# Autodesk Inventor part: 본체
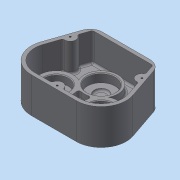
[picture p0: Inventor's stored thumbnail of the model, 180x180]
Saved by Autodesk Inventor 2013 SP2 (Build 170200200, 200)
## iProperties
Created: 2014-12
Part Number: 본체
Material: 일반
Document SubType Name: Modeling
Designer: dgall
Density: 1 g/cm^3
Author: dgall
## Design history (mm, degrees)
sketch "스케치1"
  geometry: L1 (-47, 36)-(47, 36); L2 (0, 36)-(0, -137); L3 (-32.257, -68.257)-(32.257, -68.257); L4 (0, 0)-(-32.257, -32.257); L5 (0, 0)-(32.257, -32.257); L6 (-47, 36)-(-66.327, -20.629); L7 (47, 36)-(66.327, -20.629); A1 r 36 centre (-32.257, -32.257) between (-66.327, -20.629) and (-32.257, -68.257); A2 r 36 centre (32.257, -32.257) between (32.257, -68.257) and (66.327, -20.629)
  constraints: 14 end point, 4 point on circle, 3 tangent, 2 centre point, 1 equal radius, 1 horizontal, 1 horizontal alignment, 1 midpoint, 1 perpendicular, 1 vertical alignment
  dimensions: "d3" = 36 distance from line of L4.start L1; "d4" = 94 distance of L1.start L1.end; "d5" = 36 radius of A1; "d6" = 36 distance from line of L4.end L3; "d7" = 45 deg angle of L4 L2; "d8" = 90 deg angle of L5 L4; "d9" = 32.257 horizontal distance of L5.end L4.start
extrude "돌출1" new body sketch "스케치1" distance "d10" = 51; taper "d11" = 0 deg
sketch "스케치2"
  geometry: L1 (-47, 36)-(47, 36) reference; L2 (-66.327, -20.629)-(-47, 36) reference; L3 (32.257, -68.257)-(-32.257, -68.257) reference; L4 (47, 36)-(66.327, -20.629) reference; L5 (43.423, 31)-(-43.423, 31); L6 (-43.423, 31)-(-61.595, -22.244); L7 (-32.257, -63.257)-(32.257, -63.257); L8 (61.595, -22.244)-(43.423, 31); A1 r 36 centre (-32.257, -32.257) between (-66.327, -20.629) and (-32.257, -68.257) reference; A2 r 36 centre (32.257, -32.257) between (32.257, -68.257) and (66.327, -20.629) reference; A3 r 31 centre (-32.257, -32.257) between (-61.595, -22.244) and (-32.257, -63.257); A4 r 31 centre (32.257, -32.257) between (32.257, -63.257) and (61.595, -22.244); 1 further point
  constraints: 8 end point, 4 point on circle, 2 centre point, 5 other
  dimensions: "d12" = 5 distance between parallel lines of L5 L1
extrude "돌출2" cut sketch "스케치2" distance "d13" = 41; taper "d14" = 0 deg
sketch "스케치11"
  geometry: C1 r 20 at (-32.257, -32.257); C2 r 20 at (32.257, -32.257); A1 r 36 centre (-32.257, -32.257) between (-66.327, -20.629) and (-32.257, -68.257) reference; A2 r 36 centre (32.257, -32.257) between (32.257, -68.257) and (66.327, -20.629) reference; 1 further point
  constraints: 2 centre point, 2 coincident, 1 equal radius
  dimensions: "d44" = 40 diameter of C1
extrude "돌출10" join sketch "스케치11" distance "d46" = 7; taper "d47" = -10 deg
sketch "스케치12"
  geometry: C1 r 18.766 at (0, 0) reference; C2 r 18.766 at (64.514, 0) reference; C3 r 15 at (0, 0); C4 r 15 at (64.514, 0); 1 further point
  constraints: 2 centre point, 2 coincident, 1 equal radius
  dimensions: "d48" = 30 diameter of C3
extrude "돌출11" cut sketch "스케치12" distance "d50" = 7; taper "d51" = 0 deg
sketch "스케치14"
  geometry: C1 r 24 at (0, 0); 1 further point
  constraints: 2 coincident, 1 centre point
  dimensions: "d56" = 48 diameter of C1
extrude "돌출12" join sketch "스케치14" distance "d58" = 11; taper "d59" = 0 deg
sketch "스케치15"
  geometry: C1 r 24 at (0, 0) reference; C2 r 20 at (0, 0)
  constraints: 1 centre point, 1 coincident
  dimensions: "d60" = 40 diameter of C2
extrude "돌출13" cut sketch "스케치15" distance "d62" = 12; taper "d63" = 0 deg
sketch "스케치16"
  geometry: C1 r 20 at (0, 0) reference; C2 r 10 at (0, 0)
  constraints: 1 centre point, 1 coincident
  dimensions: "d64" = 20 diameter of C2
extrude "돌출14" cut sketch "스케치16" distance "d66" = 3; taper "d67" = 0 deg
sketch "스케치17"
  geometry: C1 r 24 at (0, 0) reference; C2 r 24 at (-32.257, -32.257); C3 r 24 at (32.257, -32.257); A1 r 31 centre (-32.257, -32.257) between (-61.595, -22.244) and (-32.257, -63.257) reference; A2 r 31 centre (32.257, -32.257) between (32.257, -63.257) and (61.595, -22.244) reference
  constraints: 2 centre point, 2 coincident, 2 equal radius
extrude "돌출15" join sketch "스케치17" distance "d68" = 11; taper "d69" = 0 deg
sketch "스케치18"
  geometry: C1 r 24 at (0, 0) reference; C2 r 24 at (45.618, 45.618) reference; C3 r 17.5 at (0, 0); C4 r 17.5 at (45.618, 45.618); 1 further point
  constraints: 2 centre point, 2 coincident, 1 equal radius
  dimensions: "d70" = 35 diameter of C3
extrude "돌출16" cut sketch "스케치18" distance "d72" = 11; taper "d73" = 0 deg
sketch "스케치19"
  geometry: C1 r 17.5 at (0, 0) reference; C2 r 17.5 at (64.514, 0) reference; C3 r 7.75 at (0, 0); C4 r 7.75 at (64.514, 0); 1 further point
  constraints: 2 centre point, 2 coincident, 1 equal radius
  dimensions: "d74" = 15.5 diameter of C3
extrude "돌출17" cut sketch "스케치19" distance "d76" = 10; taper "d77" = 0 deg
sketch "스케치20"
  geometry: L1 (-61.595, -22.244)-(-43.423, 31) reference; L2 (43.423, 31)-(61.595, -22.244) reference; L3 (-47, 36)-(47, 36) reference; A1 r 8 centre (-51.614, 7) between (-54.198, -0.571) and (-49.03, 14.571); A2 r 8 centre (51.614, 7) between (49.03, 14.571) and (54.198, -0.571); 1 further point
  constraints: 6 point on line, 4 point on circle, 2 centre point, 1 equal radius, 1 horizontal alignment
  dimensions: "d78" = 29 distance from line of L3 A1.centre; "d79" = 8 radius of A1
extrude "돌출18" join sketch "스케치20" stored distance "d80" = 10; taper "d81" = 0 deg
sketch "스케치21"
  geometry: L1 (32.257, -63.257)-(-32.257, -63.257) reference; A1 r 8 centre (0, -63.257) between (8, -63.257) and (-8, -63.257); 2 further points
  constraints: 2 midpoint, 2 point on circle, 2 point on line, 1 centre point, 1 vertical alignment
  dimensions: "d82" = 8 radius of A1
extrude "돌출19" join sketch "스케치21" stored distance "d84" = 10; taper "d85" = 0 deg
sketch "스케치22"
  geometry: A1 r 8 centre (0, -63.257) between (8, -63.257) and (-8, -63.257) reference; A2 r 8 centre (-51.614, 7) between (-54.198, -0.571) and (-49.03, 14.571) reference; A3 r 8 centre (51.614, 7) between (49.03, 14.571) and (54.198, -0.571) reference; 4 further points
  constraints: 3 coincident
hole "구멍1" sketch "스케치22" at (-51.614, 7), (0, -63.257), (51.614, 7) diameter "d86" = 2.459; stored, may be unused: countersink angle "d90" = 90 deg, drill point angle "d92" = 118 deg; dims "d87" = 20, "d88" = 4, "d89" = 2, "d91" = 23
sketch "스케치23"
  geometry: L1 (47, 36)-(-47, 36) reference; 2 further points
  constraints: 1 vertical alignment, 1 other
  dimensions: "d93" = 30 distance from line of L1 point (0, 6)
feature "엠보싱1" sketch "스케치23" dims "d3" = 36, "d4" = 94, "d5" = 36, "d6" = 36, "d7" = 45 deg, "d8" = 90 deg, "d9" = 32.257, "d94" = 1, "d95" = 0
fillet "모깎기3" dims "d98" = 3
fillet "모깎기4" dims "d99" = 3
fillet "모깎기5" dims "d100" = 3
fillet "모깎기6" dims "d101" = 3
fillet "모깎기7" dims "d102" = 3
chamfer "모따기1" distance "d103" = 1; stored, may be unused: second distance "d104" = 2, angle "d105" = 45 deg
fillet "모깎기8" dims "d106" = 0.1
chamfer "모따기2" distance "d107" = 1; stored, may be unused: second distance "d108" = 2, angle "d109" = 45 deg
fillet "모깎기9" dims "d110" = 0.3
fillet "모깎기10" dims "d111" = 3
fillet "모깎기11" dims "d112" = 18
node "솔리드1"
